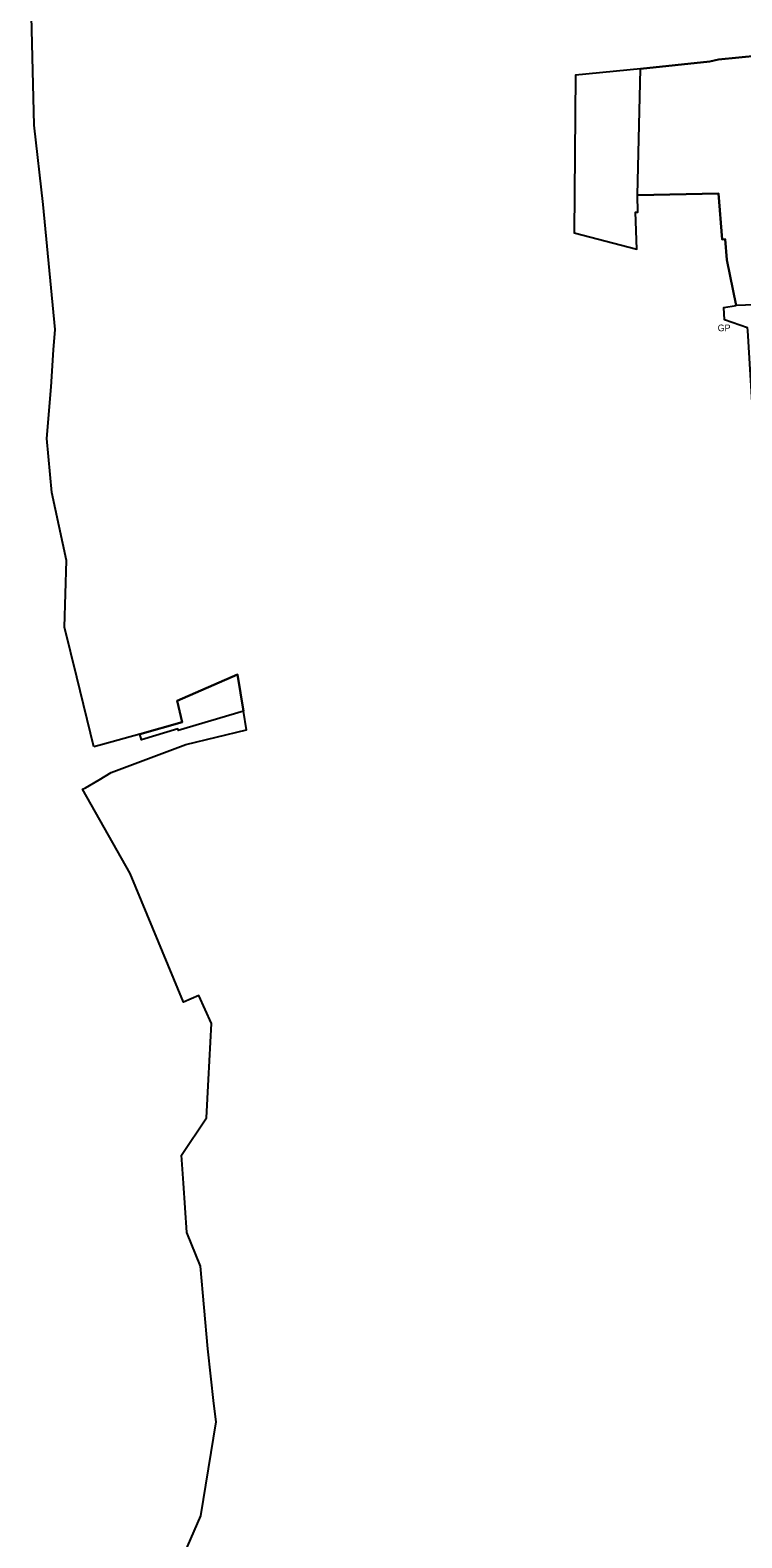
# Model space of a CAD drawing. Extents: x -615719 to -612048, y -1104937 to -1102684.
# Drawn here: x -614195.5 to -613981.5, y -1104333.4 to -1103880.3 of the extents above; entities that cross this region are included whole.
import ezdxf

# ---------------------------------------------------------------- set-up
doc = ezdxf.new("R2010")
doc.units = 0
for name, color, linetype in [('GRA_ZV', 7, 'Continuous'), ('OVNI_PRE', 7, 'Continuous'), ('OVNI_SET', 7, 'Continuous'), ('POZN', 7, 'Continuous')]:
    doc.layers.add(name, color=color, linetype=linetype)

msp = doc.modelspace()

# ---------------------------------------------------------------- linework, layer by layer
at = {"layer": 'GRA_ZV'}
for points in [[(-613902.86, -1103958.42), (-613903.38, -1103955.98), (-613905.94, -1103956.03), (-613909.32, -1103958.69), (-613916.88, -1103959.01), (-613943.72, -1103961.67), (-613983.29, -1103963.09), (-613986.08, -1103949.33), (-613986.5, -1103943.19), (-613987.43, -1103943.27), (-613988.52, -1103929.44), (-614012.92, -1103929.93), (-614012.03, -1103892), (-613991.14, -1103889.72), (-613988.53, -1103889.19), (-613970.18, -1103887.33), (-613945.41, -1103886.08)], [(-614151.34, -1104081.84), (-614133.2, -1104073.96), (-614131.37, -1104084.98), (-614150.95, -1104090.75), (-614151.1, -1104090.32), (-614162.06, -1104093.64), (-614162.55, -1104091.86), (-614149.76, -1104088.25), (-614151.34, -1104081.84)]]:
    msp.add_lwpolyline(points, dxfattribs=at)
at = {"layer": 'OVNI_PRE'}
msp.add_lwpolyline([(-613970.78, -1103877.34), (-613970.75, -1103878.04), (-613970.18, -1103887.33), (-613988.53, -1103889.19)], dxfattribs=at)
at = {"layer": 'OVNI_SET'}
for points in [[(-614188.42, -1103976.41), (-614188.01, -1103970.34), (-614191.54, -1103932.69), (-614194.32, -1103908.92), (-614195.49, -1103859.7), (-614195.24, -1103847.81), (-614192.23, -1103824.97), (-614190.77, -1103817.69), (-614187.05, -1103799.17), (-614181.08, -1103773.27), (-614177.07, -1103776.62)], [(-614012.03, -1103892), (-614031.58, -1103893.84), (-614031.96, -1103941.21), (-614013.09, -1103946.17), (-614013.5, -1103935.03), (-614012.76, -1103934.99), (-614012.92, -1103929.93)], [(-613988.53, -1103889.19), (-613991.14, -1103889.72), (-614012.03, -1103892)], [(-614012.92, -1103929.93), (-613988.52, -1103929.44), (-613987.43, -1103943.27), (-613986.5, -1103943.19), (-613986.08, -1103949.33), (-613983.29, -1103963.09)], [(-613977.34, -1104010.57), (-613979.77, -1103970.64), (-613979.82, -1103969.84), (-613986.72, -1103967.44), (-613986.99, -1103963.69), (-613983.29, -1103963.09)], [(-614176.34, -1104095.74), (-614181.49, -1104074.73), (-614185.14, -1104059.72), (-614184.55, -1104039.66), (-614189, -1104019.23), (-614190.43, -1104003.02), (-614189.17, -1103987.49), (-614188.42, -1103976.41)], [(-614174.77, -1104105.62), (-614171.09, -1104103.44), (-614148.64, -1104095.01), (-614139.61, -1104092.82), (-614130.46, -1104090.61), (-614131.37, -1104084.98), (-614133.2, -1104073.96), (-614151.34, -1104081.84), (-614149.76, -1104088.25), (-614162.55, -1104091.86), (-614173.69, -1104095.01), (-614176.34, -1104095.74)], [(-614151.34, -1104081.84), (-614133.2, -1104073.96), (-614131.37, -1104084.98)], [(-614162.55, -1104091.86), (-614149.76, -1104088.25), (-614151.34, -1104081.84)], [(-614165.4, -1104133.73), (-614179.79, -1104108.45), (-614178.83, -1104108.02), (-614174.77, -1104105.62)], [(-614141.85, -1104195.67), (-614140.93, -1104178.87), (-614144.79, -1104170.44), (-614149.37, -1104172.46), (-614158.57, -1104150.23), (-614165.4, -1104133.73)], [(-614140.26, -1104292.99), (-614142.09, -1104276.63), (-614144.31, -1104251.79), (-614148.38, -1104241.65), (-614149.4, -1104226.82), (-614149.98, -1104218.42), (-614142.48, -1104207.14), (-614141.85, -1104195.67)], [(-614129.97, -1104342.74), (-614157.84, -1104359.86), (-614158.12, -1104358.88), (-614157.21, -1104356.75), (-614144.2, -1104326.82), (-614139.61, -1104298.49), (-614140.26, -1104292.99)]]:
    msp.add_lwpolyline(points, dxfattribs=at)

# ---------------------------------------------------------------- texts
at = {"layer": 'POZN'}
msp.add_text('GP', height=2, dxfattribs=at).set_placement((-613988.8, -1103970.81))

doc.saveas('drawing.dxf')
